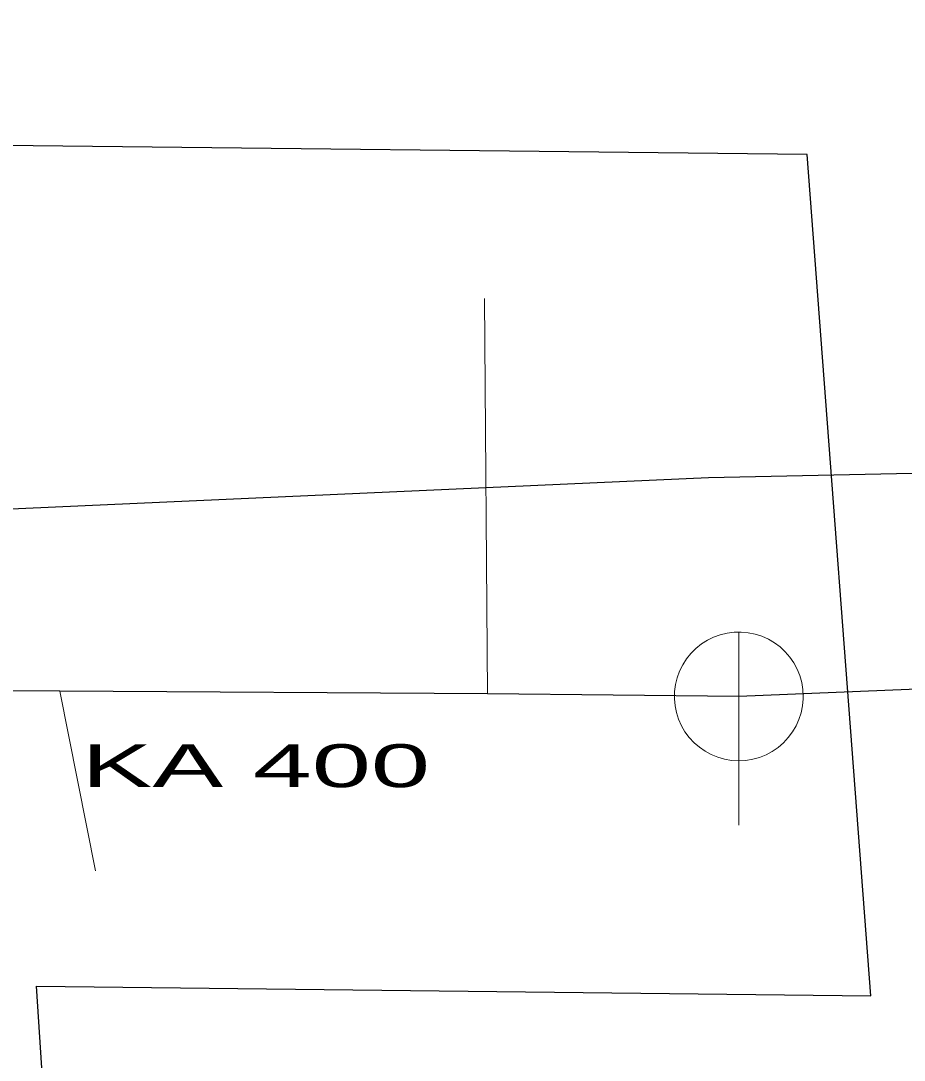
# Model space of a CAD drawing. Extents: x -688432 to -687974, y -973332 to -972704.
# Drawn here: x -688135.2 to -688121.48, y -972935.52 to -972919.38 of the extents above; entities that cross this region are included whole.
import ezdxf
from ezdxf.enums import TextEntityAlignment as Align

# ---------------------------------------------------------------- set-up
doc = ezdxf.new("R2010")
doc.units = 0
doc.header["$LTSCALE"] = 0.27
for name, color, linetype, lineweight in [('1', 7, 'Continuous', 25), ('11', 7, 'Continuous', 13), ('14', 7, 'Continuous', 25), ('17', 7, 'Continuous', 25), ('22', 7, 'Continuous', 13)]:
    doc.layers.add(name, color=color, linetype=linetype, lineweight=lineweight)

msp = doc.modelspace()

# ---------------------------------------------------------------- linework, layer by layer
at = {"layer": '1'}
msp.add_lwpolyline([(-688157.895, -972985.064), (-688131.748, -972983.489), (-688134.952, -972934.372), (-688122, -972934.52), (-688122.986, -972921.456), (-688135.938, -972921.308), (-688137.958, -972895.554), (-688157.714, -972894.909), (-688157.93, -972929.126), (-688173.215, -972938.189), (-688162.29, -972954.057)], close=True, dxfattribs=at)
at = {"layer": '11'}
for p, q in [((-688128, -972923.69), (-688127.949, -972929.829)), ((-688134.039, -972932.579), (-688134.59, -972929.789))]:
    msp.add_line(p, q, dxfattribs=at)
at = {"layer": '14'}
for points in [[(-688102.239, -972928.739), (-688109.82, -972929.289), (-688124.05, -972929.87)], [(-688124.05, -972929.87), (-688127.949, -972929.829), (-688134.59, -972929.789), (-688139.03, -972929.76)]]:
    msp.add_lwpolyline(points, dxfattribs=at)
at = {"layer": '17'}
msp.add_lwpolyline([(-688142.539, -972926.989), (-688136.969, -972927.03), (-688124.52, -972926.469), (-688116.5, -972926.3), (-688115.02, -972926.289), (-688112.359, -972926.21), (-688100.73, -972925.699), (-688087.609, -972926.17), (-688083.969, -972927.539), (-688080.94, -972929.1), (-688078.329, -972931.09), (-688076.37, -972933.14), (-688074.449, -972935.62), (-688070.85, -972940.129), (-688068.85, -972942.57), (-688067.02, -972944.8), (-688063.62, -972948.98), (-688063.329, -972949.34), (-688059.6, -972954.02), (-688058.039, -972955.829), (-688055.76, -972958.48), (-688051.969, -972962.76), (-688050.239, -972964.93)], dxfattribs=at)
at = {"layer": '22'}
msp.add_line((-688124.05, -972931.87), (-688124.049, -972928.87), dxfattribs=at)
msp.add_lwpolyline([(-688123.05, -972929.87), (-688123.055, -972929.761), (-688123.073, -972929.653), (-688123.103, -972929.547), (-688123.143, -972929.446), (-688123.195, -972929.349), (-688123.257, -972929.259), (-688123.329, -972929.176), (-688123.409, -972929.102), (-688123.497, -972929.036), (-688123.591, -972928.981), (-688123.691, -972928.936), (-688123.796, -972928.903), (-688123.903, -972928.881), (-688124.012, -972928.871), (-688124.122, -972928.873), (-688124.23, -972928.887), (-688124.337, -972928.912), (-688124.44, -972928.949), (-688124.538, -972928.998), (-688124.63, -972929.056), (-688124.716, -972929.125), (-688124.793, -972929.202), (-688124.862, -972929.288), (-688124.921, -972929.38), (-688124.969, -972929.478), (-688125.006, -972929.581), (-688125.032, -972929.688), (-688125.046, -972929.796), (-688125.049, -972929.906), (-688125.039, -972930.015), (-688125.018, -972930.122), (-688124.984, -972930.226), (-688124.94, -972930.326), (-688124.885, -972930.421), (-688124.819, -972930.509), (-688124.745, -972930.589), (-688124.662, -972930.661), (-688124.572, -972930.723), (-688124.476, -972930.775), (-688124.374, -972930.816), (-688124.269, -972930.846), (-688124.161, -972930.864), (-688124.051, -972930.87), (-688123.942, -972930.864), (-688123.834, -972930.846), (-688123.729, -972930.817), (-688123.627, -972930.776), (-688123.53, -972930.724), (-688123.44, -972930.662), (-688123.357, -972930.591), (-688123.282, -972930.511), (-688123.217, -972930.423), (-688123.161, -972930.329), (-688123.117, -972930.229), (-688123.083, -972930.125), (-688123.061, -972930.017), (-688123.051, -972929.908)], close=True, dxfattribs=at)

# ---------------------------------------------------------------- texts
at = {"layer": '1', "width": 1.85}
msp.add_text('KA 400', height=0.6667, dxfattribs=at).set_placement((-688131.549, -972931.28), align=Align.CENTER)
msp.add_text('KA 400', height=0.6667, dxfattribs=at).set_placement((-688131.549, -972931.28), align=Align.CENTER)
msp.add_text('KA 400', height=0.6667, dxfattribs=at).set_placement((-688131.549, -972931.28), align=Align.CENTER)
msp.add_text('KA 400', height=0.6667, dxfattribs=at).set_placement((-688131.549, -972931.28), align=Align.CENTER)
msp.add_text('KA 400', height=0.6667, dxfattribs=at).set_placement((-688131.549, -972931.28), align=Align.CENTER)

doc.saveas('drawing.dxf')
